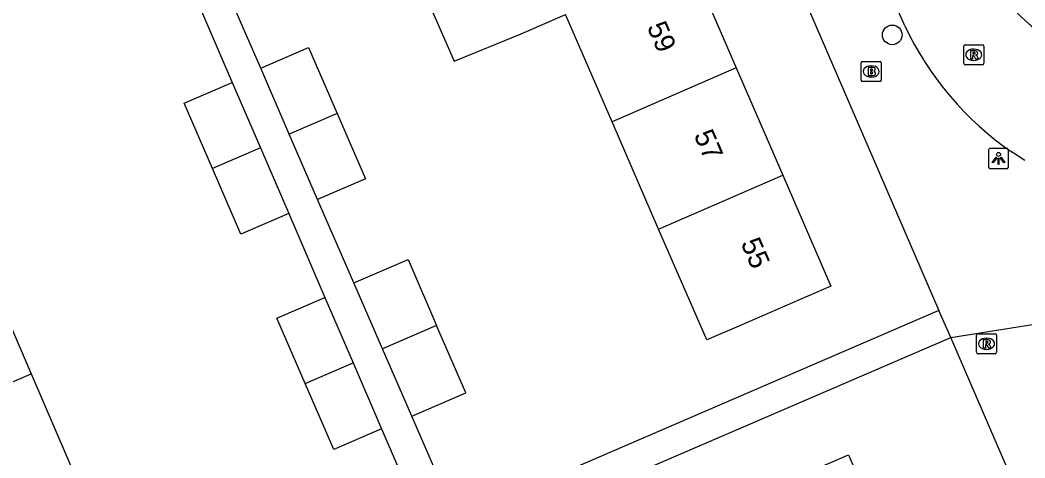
# Model space of a CAD drawing. Extents: x 159353 to 160616, y 385893 to 387321.
# Drawn here: x 159638.3 to 159688.4, y 386300.6 to 386322.4 of the extents above; entities that cross this region are included whole.
import ezdxf

# ---------------------------------------------------------------- set-up
doc = ezdxf.new("R2010")
doc.units = 0
for name, color, linetype in [('IMGEO_Boom', 7, 'Continuous'), ('IMGEO_Brandkraan', 7, 'Continuous'), ('IMGEO_Lichtpunt', 7, 'Continuous'), ('IMGEO_Pand', 7, 'Continuous'), ('IMGEO_Pand_nummerreeks', 7, 'Continuous'), ('IMGEO_Rijbaan_lokaal_open', 7, 'Continuous'), ('IMGEO_Rioolput', 7, 'Continuous'), ('IMGEO_Voetpad_open', 7, 'Continuous')]:
    doc.layers.add(name, color=color, linetype=linetype)

msp = doc.modelspace()

# ---------------------------------------------------------------- linework, layer by layer
at = {"layer": 'IMGEO_Boom'}
msp.add_circle((159681.767, 386321.681), 0.489, dxfattribs=at)
at = {"layer": 'IMGEO_Brandkraan'}
for p, q in [((159680.216, 386319.431), (159680.216, 386320.283)), ((159680.291, 386320.357), (159681.143, 386320.357)), ((159680.704, 386320.137), (159680.729, 386320.137)), ((159681.217, 386320.283), (159681.217, 386319.431)), ((159680.727, 386319.577), (159680.702, 386319.577)), ((159681.143, 386319.357), (159680.291, 386319.357))]:
    msp.add_line(p, q, dxfattribs=at)
for points in [[(159680.216, 386319.431), (159680.216, 386320.283)], [(159680.291, 386320.357), (159681.143, 386320.357)], [(159680.564, 386320.057), (159680.564, 386319.657), (159680.777, 386319.657)], [(159680.795, 386320.057), (159680.564, 386320.057)], [(159680.743, 386319.976), (159680.689, 386319.976), (159680.689, 386319.9)], [(159681.217, 386320.283), (159681.217, 386319.431)], [(159680.689, 386319.9), (159680.742, 386319.9)], [(159680.751, 386319.824), (159680.689, 386319.824), (159680.689, 386319.743)], [(159680.689, 386319.743), (159680.751, 386319.743)], [(159681.143, 386319.357), (159680.291, 386319.357)]]:
    msp.add_lwpolyline(points, dxfattribs=at)
for centre, radius, start, end in [((159680.293, 386320.281), 0.0765, 91.552, 178.448), ((159680.293, 386320.281), 0.0765, 91.552, 178.448), ((159680.744, 386319.938), 0.0379, 267.8285, 90.9355), ((159680.799, 386319.912), 0.145, 59.4692, 91.5367), ((159680.824, 386319.959), 0.0922, 285.5137, 58.1501), ((159681.141, 386320.281), 0.0765, 1.552, 88.448), ((159681.141, 386320.281), 0.0765, 1.552, 88.448), ((159680.293, 386319.433), 0.0765, 181.552, 268.448), ((159680.293, 386319.433), 0.0765, 181.552, 268.448), ((159680.752, 386319.783), 0.0404, 269.8759, 90.5077), ((159680.783, 386319.908), 0.251, 268.6676, 293.5347), ((159680.829, 386319.767), 0.105, 301.3115, 78.989), ((159681.141, 386319.433), 0.0765, 271.552, 358.448), ((159681.141, 386319.433), 0.0765, 271.552, 358.448)]:
    msp.add_arc(centre, radius, start, end, dxfattribs=at)
for centre, major_axis, ratio, start_param, end_param in [((159680.703, 386319.857), (-0.387, 0.002), 0.722429, 4.712389, 7.853982), ((159680.728, 386319.857), (-0.39, 0.002), 0.717154, 1.570796, 4.712389)]:
    msp.add_ellipse(centre, major_axis=major_axis, ratio=ratio, start_param=start_param, end_param=end_param, dxfattribs=at)
at = {"layer": 'IMGEO_Lichtpunt'}
for p, q in [((159686.557, 386315.923), (159686.557, 386315.116)), ((159686.557, 386315.923), (159686.557, 386315.116)), ((159687.459, 386316.018), (159686.651, 386316.018)), ((159687.459, 386316.018), (159686.651, 386316.018)), ((159687.553, 386315.116), (159687.553, 386315.923)), ((159687.553, 386315.116), (159687.553, 386315.923)), ((159686.651, 386315.022), (159687.459, 386315.022)), ((159686.651, 386315.022), (159687.459, 386315.022))]:
    msp.add_line(p, q, dxfattribs=at)
for points in [[(159686.931, 386315.587), (159686.97, 386315.559), (159686.782, 386315.297), (159686.744, 386315.324), (159686.931, 386315.587)], [(159687.033, 386315.539), (159687.08, 386315.539), (159687.08, 386315.217), (159687.033, 386315.217), (159687.033, 386315.539)], [(159687.143, 386315.559), (159687.181, 386315.586), (159687.368, 386315.324), (159687.329, 386315.296), (159687.143, 386315.559)]]:
    msp.add_lwpolyline(points, dxfattribs=at)
msp.add_circle((159687.056, 386315.721), 0.0994, dxfattribs=at)
for centre, start, end in [((159686.651, 386315.923), 90, 180), ((159686.651, 386315.923), 90, 180), ((159687.459, 386315.923), 0, 90), ((159687.459, 386315.923), 0, 90), ((159686.651, 386315.116), 180, 270), ((159686.651, 386315.116), 180, 270), ((159687.459, 386315.116), 270, 0), ((159687.459, 386315.116), 270, 360)]:
    msp.add_arc(centre, 0.0946, start, end, dxfattribs=at)
at = {"layer": 'IMGEO_Pand'}
for points in [[(159663.18, 386328.046), (159660.975, 386327.089), (159657.656, 386325.649), (159659.948, 386320.368), (159663.294, 386321.739), (159665.499, 386322.697)], [(159671.682, 386325.38), (159674, 386320.031)], [(159667.817, 386317.348), (159665.499, 386322.697)], [(159650.328, 386320.017), (159652.709, 386321.046), (159654.128, 386317.763)], [(159651.748, 386316.73), (159650.328, 386320.017)], [(159674, 386320.031), (159667.817, 386317.348)], [(159674, 386320.031), (159676.318, 386314.683)], [(159647.923, 386315.023), (159646.515, 386318.281), (159648.897, 386319.31)], [(159648.897, 386319.31), (159650.306, 386316.05)], [(159654.128, 386317.763), (159651.748, 386316.73)], [(159654.128, 386317.763), (159655.534, 386314.507), (159653.153, 386313.478)], [(159670.136, 386311.999), (159667.817, 386317.348)], [(159653.153, 386313.478), (159651.748, 386316.73)], [(159650.306, 386316.05), (159647.923, 386315.023)], [(159650.306, 386316.05), (159651.722, 386312.771)], [(159651.722, 386312.771), (159649.34, 386311.742), (159647.923, 386315.023)], [(159676.318, 386314.683), (159678.713, 386309.157), (159674.126, 386307.169), (159672.529, 386306.477), (159670.136, 386311.999)], [(159670.136, 386311.999), (159676.318, 386314.683)], [(159654.965, 386309.319), (159657.659, 386310.486), (159659.082, 386307.2)], [(159636.592, 386310.142), (159638.901, 386304.783)], [(159656.39, 386306.031), (159654.965, 386309.319)], [(159652.541, 386304.305), (159651.133, 386307.563), (159653.515, 386308.592)], [(159653.515, 386308.592), (159654.924, 386305.332)], [(159659.082, 386307.2), (159656.39, 386306.031)], [(159657.843, 386302.678), (159660.536, 386303.844), (159659.082, 386307.2)], [(159657.843, 386302.678), (159656.39, 386306.031)], [(159652.541, 386304.305), (159654.924, 386305.332)], [(159654.924, 386305.332), (159656.34, 386302.053)], [(159632.71, 386302.116), (159638.901, 386304.783)], [(159638.901, 386304.783), (159641.21, 386299.424)], [(159656.34, 386302.053), (159653.958, 386301.024), (159652.541, 386304.305)], [(159675.796, 386292.416), (159673.355, 386298.054), (159674.994, 386298.764), (159679.582, 386300.75), (159682.023, 386295.112)]]:
    msp.add_lwpolyline(points, dxfattribs=at)
at = {"layer": 'IMGEO_Rijbaan_lokaal_open'}
for points in [[(159682.399, 386322.126), (159681.53, 386324.098)], [(159688.37, 386315.426), (159687.739, 386315.836)]]:
    msp.add_lwpolyline(points, dxfattribs=at)
for centre, radius, start, end in [((159695.027, 386329.622), 9.82, 198.4392, 269.9012), ((159696.581, 386328.754), 15.654, 205.0501, 235.6102)]:
    msp.add_arc(centre, radius, start, end, dxfattribs=at)
at = {"layer": 'IMGEO_Rioolput'}
for p, q in [((159685.323, 386320.264), (159685.323, 386321.116)), ((159685.398, 386321.19), (159686.25, 386321.19)), ((159685.811, 386320.97), (159685.836, 386320.97)), ((159686.324, 386321.116), (159686.324, 386320.264)), ((159686.25, 386320.19), (159685.398, 386320.19)), ((159685.834, 386320.41), (159685.809, 386320.41)), ((159685.96, 386305.862), (159685.96, 386306.714)), ((159686.035, 386306.788), (159686.887, 386306.788)), ((159686.448, 386306.568), (159686.473, 386306.568)), ((159686.961, 386306.714), (159686.961, 386305.862)), ((159686.471, 386306.008), (159686.446, 386306.008)), ((159686.887, 386305.788), (159686.035, 386305.788))]:
    msp.add_line(p, q, dxfattribs=at)
for points in [[(159685.323, 386320.264), (159685.323, 386321.116)], [(159685.398, 386321.19), (159686.25, 386321.19)], [(159686.324, 386321.116), (159686.324, 386320.264)], [(159685.912, 386320.888), (159685.66, 386320.89), (159685.66, 386320.49)], [(159685.66, 386320.49), (159685.784, 386320.49), (159685.784, 386320.652), (159685.795, 386320.652)], [(159685.838, 386320.809), (159685.784, 386320.809), (159685.784, 386320.728)], [(159685.784, 386320.728), (159685.836, 386320.728)], [(159685.842, 386320.623), (159685.913, 386320.49), (159686.053, 386320.49), (159685.988, 386320.616)], [(159686.25, 386320.19), (159685.398, 386320.19)], [(159685.96, 386305.862), (159685.96, 386306.714)], [(159686.035, 386306.788), (159686.887, 386306.788)], [(159686.549, 386306.486), (159686.297, 386306.488), (159686.297, 386306.088)], [(159686.961, 386306.714), (159686.961, 386305.862)], [(159686.297, 386306.088), (159686.421, 386306.088), (159686.421, 386306.25), (159686.432, 386306.25)], [(159686.475, 386306.407), (159686.421, 386306.407), (159686.421, 386306.326)], [(159686.421, 386306.326), (159686.473, 386306.326)], [(159686.479, 386306.221), (159686.55, 386306.088), (159686.69, 386306.088), (159686.625, 386306.214)], [(159686.887, 386305.788), (159686.035, 386305.788)]]:
    msp.add_lwpolyline(points, dxfattribs=at)
for centre, radius, start, end in [((159685.4, 386321.114), 0.0765, 91.552, 178.448), ((159685.4, 386321.114), 0.0765, 91.552, 178.448), ((159686.248, 386321.114), 0.0765, 1.552, 88.448), ((159686.248, 386321.114), 0.0765, 1.552, 88.448), ((159685.794, 386320.599), 0.0533, 26.0293, 88.6989), ((159685.82, 386320.917), 0.19, 274.7715, 282.9687), ((159685.844, 386320.713), 0.0964, 77.0061, 93.1865), ((159685.858, 386320.77), 0.0378, 276.6634, 79.6772), ((159685.911, 386320.778), 0.109, 350.3612, 89.416), ((159685.909, 386320.778), 0.112, 277.5842, 350.9817), ((159685.893, 386320.563), 0.108, 29.5134, 73.7905), ((159685.4, 386320.266), 0.0765, 181.552, 268.448), ((159685.4, 386320.266), 0.0765, 181.552, 268.448), ((159686.248, 386320.266), 0.0765, 271.552, 358.448), ((159686.248, 386320.266), 0.0765, 271.552, 358.448), ((159686.037, 386306.712), 0.0765, 91.552, 178.448), ((159686.037, 386306.712), 0.0765, 91.552, 178.448), ((159686.548, 386306.376), 0.109, 350.3612, 89.416), ((159686.885, 386306.712), 0.0765, 1.552, 88.448), ((159686.885, 386306.712), 0.0765, 1.552, 88.448), ((159686.431, 386306.197), 0.0533, 26.0293, 88.6989), ((159686.457, 386306.515), 0.19, 274.7715, 282.9687), ((159686.481, 386306.311), 0.0964, 77.0061, 93.1865), ((159686.495, 386306.368), 0.0378, 276.6634, 79.6772), ((159686.546, 386306.376), 0.112, 277.5842, 350.9817), ((159686.53, 386306.161), 0.108, 29.5134, 73.7905), ((159686.037, 386305.864), 0.0765, 181.552, 268.448), ((159686.037, 386305.864), 0.0765, 181.552, 268.448), ((159686.885, 386305.864), 0.0765, 271.552, 358.448), ((159686.885, 386305.864), 0.0765, 271.552, 358.448)]:
    msp.add_arc(centre, radius, start, end, dxfattribs=at)
for centre, major_axis, ratio, start_param, end_param in [((159685.81, 386320.69), (-0.387, 0.002), 0.722429, 4.712389, 7.853982), ((159685.835, 386320.69), (-0.39, 0.002), 0.717154, 1.570796, 4.712389), ((159686.447, 386306.288), (-0.387, 0.002), 0.722429, 4.712389, 7.853982), ((159686.472, 386306.288), (-0.39, 0.002), 0.717154, 1.570796, 4.712389)]:
    msp.add_ellipse(centre, major_axis=major_axis, ratio=ratio, start_param=start_param, end_param=end_param, dxfattribs=at)
at = {"layer": 'IMGEO_Voetpad_open'}
for points in [[(159650.328, 386320.017), (159648.516, 386324.176)], [(159647.104, 386323.487), (159648.897, 386319.31)], [(159677.65, 386322.87), (159684.092, 386307.943)], [(159654.965, 386309.319), (159653.153, 386313.478)], [(159651.722, 386312.771), (159653.515, 386308.592)], [(159684.092, 386307.943), (159660.056, 386297.569), (159659.735, 386298.309), (159657.843, 386302.678)], [(159684.675, 386306.593), (159684.092, 386307.943)], [(159684.675, 386306.593), (159689.161, 386307.308)], [(159662.967, 386297.224), (159684.675, 386306.593)], [(159701.006, 386268.753), (159684.675, 386306.593)], [(159656.34, 386302.053), (159658.516, 386297.013), (159644.802, 386291.091)]]:
    msp.add_lwpolyline(points, dxfattribs=at)

# ---------------------------------------------------------------- texts
at = {"layer": 'IMGEO_Pand_nummerreeks'}
for s, p in [('59', (159669.537, 386322.081)), ('57', (159671.872, 386316.693)), ('55', (159674.207, 386311.305))]:
    msp.add_text(s, height=1, rotation=293.4329, dxfattribs=at).set_placement(p)

doc.saveas('drawing.dxf')
